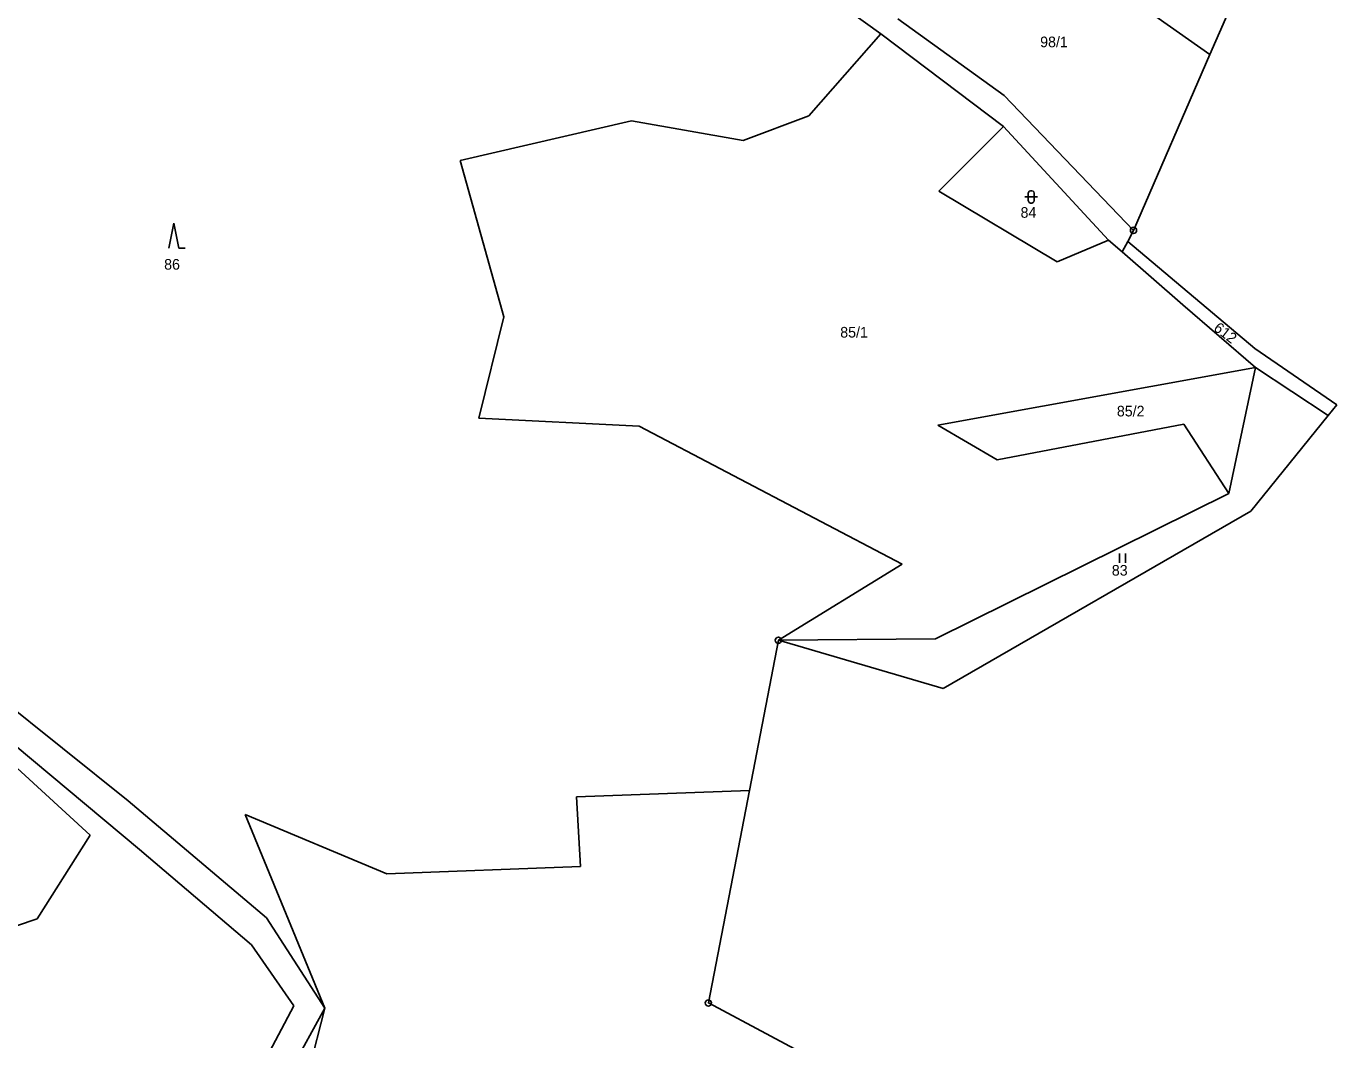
# Model space of a CAD drawing. Extents: x -794421 to -792735, y -1117671 to -1115559.
# Drawn here: x -793109.5 to -792899.6, y -1117244.8 to -1117082.5 of the extents above; entities that cross this region are included whole.
import ezdxf

# ---------------------------------------------------------------- set-up
doc = ezdxf.new("R2010")
doc.units = 0
for name, color, linetype in [('Vrstva 1', 7, 'Continuous'), ('Vrstva 14', 7, 'Continuous'), ('Vrstva 23', 7, 'Continuous'), ('Vrstva 28', 7, 'Continuous'), ('Vrstva 4', 7, 'Continuous')]:
    doc.layers.add(name, color=color, linetype=linetype)

msp = doc.modelspace()

# ---------------------------------------------------------------- linework, layer by layer
at = {"layer": 'Vrstva 1'}
for p, q in [((-792956.35, -1117061.26), (-792919.93, -1117087.01)), ((-792977.94, -1117079.87), (-792972.66, -1117083.66)), ((-792969.93, -1117081.25), (-792952.88, -1117093.55)), ((-792972.66, -1117083.66), (-792984.15, -1117096.78)), ((-792953.01, -1117098.53), (-792972.66, -1117083.66)), ((-792952.88, -1117093.55), (-792932.18, -1117115.16)), ((-792984.15, -1117096.78), (-792994.69, -1117100.75)), ((-793012.56, -1117097.63), (-793039.99, -1117103.98)), ((-792994.69, -1117100.75), (-793012.56, -1117097.63)), ((-792963.36, -1117108.89), (-792953.01, -1117098.53)), ((-792953.01, -1117098.53), (-792936.17, -1117116.69)), ((-793039.99, -1117103.98), (-793032.99, -1117129)), ((-792944.38, -1117120.21), (-792963.36, -1117108.89)), ((-792936.17, -1117116.69), (-792944.38, -1117120.21)), ((-792933.99, -1117118.59), (-792936.17, -1117116.69)), ((-792933.1, -1117116.93), (-792933.99, -1117118.59)), ((-792924.25, -1117127.06), (-792933.99, -1117118.59)), ((-792912.65, -1117137.09), (-792924.25, -1117127.06)), ((-793032.99, -1117129), (-793037.01, -1117145.24)), ((-792912.65, -1117137.09), (-792963.53, -1117146.34)), ((-792916.89, -1117157.3), (-792912.65, -1117137.09)), ((-792912.65, -1117137.09), (-792901.01, -1117144.78)), ((-793037.01, -1117145.24), (-793011.33, -1117146.52)), ((-793011.33, -1117146.52), (-792969.23, -1117168.62)), ((-792963.53, -1117146.34), (-792954.02, -1117151.89)), ((-792954.02, -1117151.89), (-792924.12, -1117146.19)), ((-792924.12, -1117146.19), (-792916.89, -1117157.3)), ((-792963.9, -1117180.54), (-792916.89, -1117157.3)), ((-792969.23, -1117168.62), (-792989.05, -1117180.78)), ((-792989.05, -1117180.78), (-792963.9, -1117180.54)), ((-793093.15, -1117206.52), (-793114.94, -1117189.09)), ((-793115.3, -1117194.27), (-793091.34, -1117214.31)), ((-793115.19, -1117197.4), (-793099.28, -1117212.02)), ((-793021.4, -1117205.86), (-792993.69, -1117204.85)), ((-793021.4, -1117205.86), (-793020.74, -1117217.02)), ((-793071.02, -1117225.22), (-793093.15, -1117206.52)), ((-793051.75, -1117218.2), (-793074.43, -1117208.67)), ((-793074.43, -1117208.67), (-793061.68, -1117239.68)), ((-793099.28, -1117212.02), (-793107.76, -1117225.41)), ((-793091.34, -1117214.31), (-793073.44, -1117229.58)), ((-793020.74, -1117217.02), (-793051.75, -1117218.2)), ((-793107.76, -1117225.41), (-793124.49, -1117230.97)), ((-793061.68, -1117239.68), (-793071.02, -1117225.22)), ((-793073.44, -1117229.58), (-793066.62, -1117239.34)), ((-793066.62, -1117239.34), (-793076.81, -1117258.54)), ((-793061.68, -1117239.68), (-793073.4, -1117260.98)), ((-793073.28, -1117284.7), (-793061.68, -1117239.68))]:
    msp.add_line(p, q, dxfattribs=at)
at = {"layer": 'Vrstva 23'}
for p, q in [((-792949.06, -1117109.19), (-792948.96, -1117108.99)), ((-792949.06, -1117110.39), (-792949.06, -1117109.19)), ((-792948.96, -1117108.99), (-792948.86, -1117108.89)), ((-792948.86, -1117108.89), (-792948.66, -1117108.79)), ((-792948.66, -1117108.79), (-792948.46, -1117108.79)), ((-792948.46, -1117108.79), (-792948.26, -1117108.89)), ((-792948.26, -1117108.89), (-792948.16, -1117108.99)), ((-792948.16, -1117108.99), (-792948.06, -1117109.19)), ((-792948.06, -1117109.19), (-792948.06, -1117110.39)), ((-792949.56, -1117109.79), (-792947.56, -1117109.79)), ((-792948.96, -1117110.59), (-792949.06, -1117110.39)), ((-792948.86, -1117110.69), (-792948.96, -1117110.59)), ((-792948.66, -1117110.79), (-792948.86, -1117110.69)), ((-792948.46, -1117110.79), (-792948.66, -1117110.79)), ((-792948.26, -1117110.69), (-792948.46, -1117110.79)), ((-792948.16, -1117110.59), (-792948.26, -1117110.69)), ((-792948.06, -1117110.39), (-792948.16, -1117110.59)), ((-793086.65, -1117118), (-793085.85, -1117114)), ((-793085.85, -1117114), (-793085.05, -1117118)), ((-793085.05, -1117118), (-793084.05, -1117118)), ((-792934.43, -1117168.38), (-792934.43, -1117166.88)), ((-792933.43, -1117166.88), (-792933.43, -1117168.38))]:
    msp.add_line(p, q, dxfattribs=at)
at = {"layer": 'Vrstva 28'}
for centre, radius in [((-792932.18, -1117115.16), 0.5), ((-792932.18, -1117115.16), 0.01), ((-792989.05, -1117180.78), 0.5), ((-792989.05, -1117180.78), 0.01), ((-793000.25, -1117238.87), 0.5), ((-793000.25, -1117238.87), 0.01)]:
    msp.add_circle(centre, radius, dxfattribs=at)
at = {"layer": 'Vrstva 4'}
for p, q in [((-792903.79, -1117049.93), (-792919.93, -1117087.01)), ((-792919.93, -1117087.01), (-792932.18, -1117115.16)), ((-792932.18, -1117115.16), (-792933.1, -1117116.93)), ((-792933.1, -1117116.93), (-792912.74, -1117134.08)), ((-792912.74, -1117134.08), (-792899.62, -1117143.07)), ((-792901.01, -1117144.78), (-792913.41, -1117160.11)), ((-792899.62, -1117143.07), (-792901.01, -1117144.78)), ((-792913.41, -1117160.11), (-792962.63, -1117188.49)), ((-792989.05, -1117180.78), (-792993.69, -1117204.85)), ((-792962.63, -1117188.49), (-792989.05, -1117180.78)), ((-792993.69, -1117204.85), (-793000.25, -1117238.87)), ((-793000.25, -1117238.87), (-792931.78, -1117275.26))]:
    msp.add_line(p, q, dxfattribs=at)

# ---------------------------------------------------------------- texts
at = {"layer": 'Vrstva 14'}
for s, p in [('98/1', (-792947.123, -1117085.82)), ('84', (-792950.262, -1117113.13)), ('86', (-793087.407, -1117121.44)), ('85/1', (-792979.139, -1117132.31)), ('85/2', (-792934.836, -1117144.94)), ('83', (-792935.647, -1117170.43))]:
    msp.add_text(s, height=1.7, dxfattribs=at).set_placement(p)
msp.add_text('612', height=1.7, rotation=322.64163, dxfattribs=at).set_placement((-792919.476, -1117131.074))

doc.saveas('drawing.dxf')
